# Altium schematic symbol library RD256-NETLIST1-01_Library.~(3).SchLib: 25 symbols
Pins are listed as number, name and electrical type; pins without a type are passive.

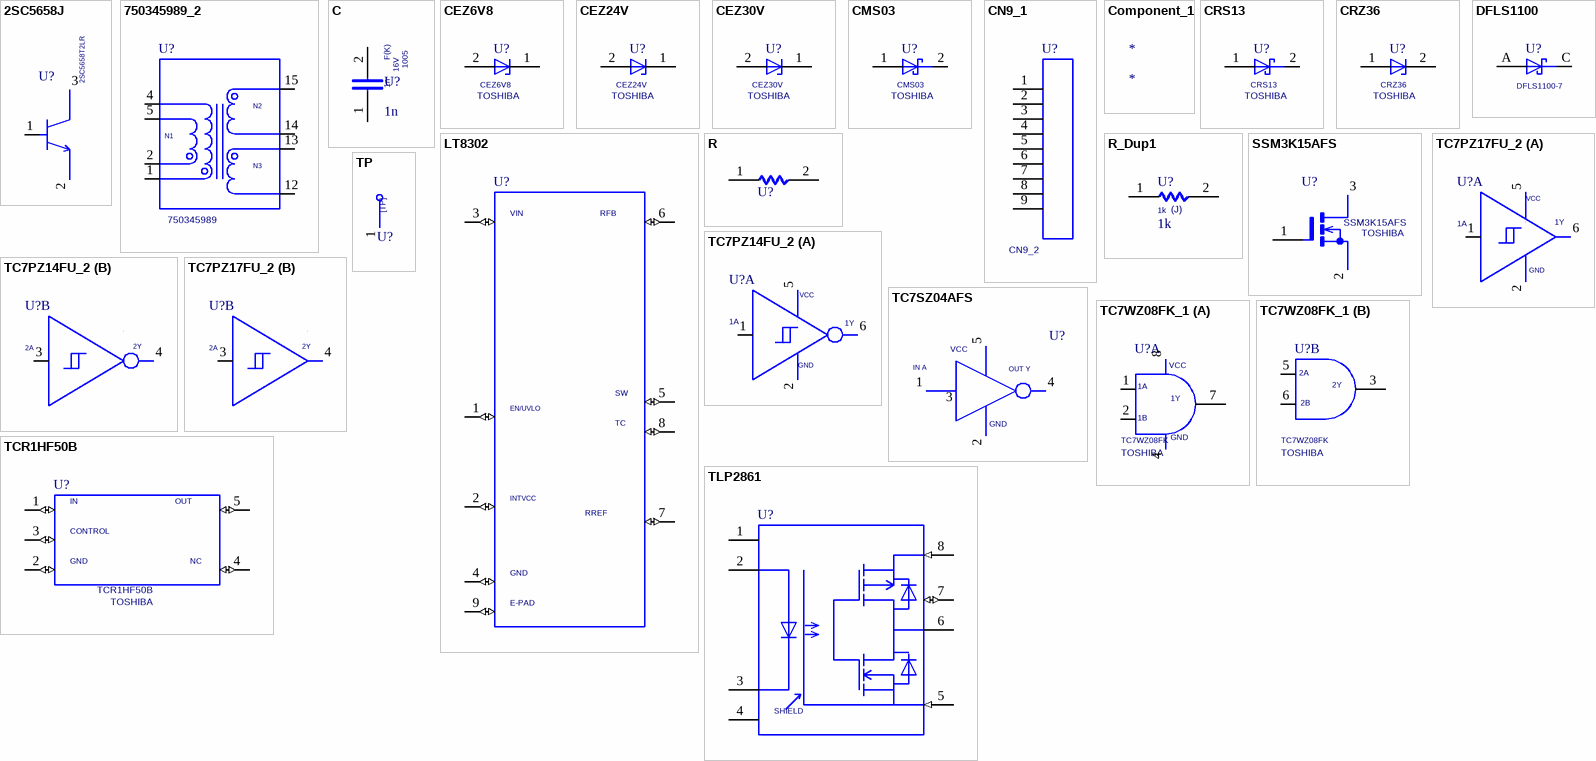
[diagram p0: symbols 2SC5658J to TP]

## 2SC5658J
designator U?, comment 2SC5658T2LR
TIME: 09:39:04; UPDATEUSER: 19910145; UPDATETIME: 15:12:10; SAVECOUNT: 8; COMP: 2SC5658J; VENDOR: ROHM; SAVEAREA0: -6194,-158,18648,15662; PSPICETEMPLATE: X^@REFDES %C %B %E @MODEL; ORIGINALSYMBOLORIGIN: (0,0); Altium-Right: 20; Altium-Bottom: 80
simulation model 2SC5658J
pins: 1 B, 2 E, 3 C

## 750345989_2
designator U?, comment 750345989
TIME: 11:55:02; UPDATEUSER: t5459927; UPDATETIME: 19:39:05; SAVECOUNT: 3; COMP: 750345989_2; PSPICETEMPLATE: X^@REFDES %1 %2 %3 %4 %5 %6 %7 %8 @MODEL; OriginalSymbolOrigin: (0,0); Altium-Right: 80; Altium-Bottom: 100
simulation model 750345989_2
pins: 1 4 (io), 2 5 (io), 4 1 (io), 5 2 (io), 12 (io), 13 (io), 14 (io), 15 (io)

## C
designator U?, comment 1n  VAL1: F(K)  SIZE: 1005  VOLTAGE: 16V
TIME: 11:55:01; UPDATEUSER: HP_Z8_KEYSHOT; SAVECOUNT: 2; COMP: C; TC1: 0; PSPICETEMPLATE: C^@REFDES %1 %2 ?TOLERANCE¦C^@REFDES¦ @VALUE ?IC/IC=@IC/ TC=@TC1,@TC2 ?TOLERANCE¦\n.model C^@REFDES CAP C=1 DEV=@TOLERANCE% TC1=@TC1 TC2=@TC2 VC1=@VC1 VC2=@VC2¦; ORIGINALSYMBOLORIGIN: (0,0); Altium-Right: 20; Altium-Bottom: 10
simulation model C
pins: 1, 2

## CEZ6V8
designator U?  VENDOR: TOSHIBA
TIME: 14:49:55; UPDATEUSER: fukuda-y; UPDATETIME: 08:18:42; SAVECOUNT: 6; SAVEAREA0: -4630,-153,17114,13055; PSPICETEMPLATE: X^@REFDES %A %C @MODEL; ORIGINALSYMBOLORIGIN: (0,0); Altium-Right: 10; Altium-Bottom: 20
simulation model CEZ6V8
pins: 1 C, 2 A

## CEZ24V
designator U?  VENDOR: TOSHIBA
TIME: 14:49:55; UPDATEUSER: fukuda-y; UPDATETIME: 08:18:42; SAVECOUNT: 6; SAVEAREA0: -4630,-153,17114,13055; PSPICETEMPLATE: X^@REFDES %A %C @MODEL; ORIGINALSYMBOLORIGIN: (0,0); Altium-Right: 10; Altium-Bottom: 20
simulation model CEZ24V
pins: 1 C, 2 A

## CEZ30V
designator U?  VENDOR: TOSHIBA
TIME: 14:49:55; UPDATEUSER: fukuda-y; UPDATETIME: 08:18:42; SAVECOUNT: 6; SAVEAREA0: -4630,-153,17114,13055; PSPICETEMPLATE: X^@REFDES %C %A @MODEL; ORIGINALSYMBOLORIGIN: (0,0); Altium-Right: 10; Altium-Bottom: 20
simulation model CEZ30V
pins: 1 C, 2 A

## CMS03
designator U?  VENDOR: TOSHIBA
TIME: 14:49:55; UPDATEUSER: fukuda-y; UPDATETIME: 08:16:22; SAVECOUNT: 9; SAVEAREA0: -4630,-153,17114,13055; PSPICETEMPLATE: X^@REFDES %A %C @MODEL; ORIGINALSYMBOLORIGIN: (0,0); Altium-Right: 20
simulation model CMS03
pins: 1 A, 2 C

## CN9_1
designator U?, comment CN9_2
TIME: 11:55:03; UPDATEUSER: HP_Z8_KEYSHOT; SAVECOUNT: 2; PSPICETEMPLATE: X^@REFDES %1 %2 %3 %4 %5 %6 %7 %8 %9 %10 %M1 %M2 @MODEL; COMP: CN9_1; USER_VALUE: XG4A-1031; OriginalSymbolOrigin: (0,0); Altium-Right: 20; Altium-Bottom: 120
simulation model CN9_1
pins: 1, 2, 3, 4, 5, 6, 7, 8, 9

## Component_1
designator *

## CRS13
designator U?  VENDOR: TOSHIBA
TIME: 14:49:55; UPDATEUSER: fukuda-y; UPDATETIME: 08:18:42; SAVECOUNT: 6; SAVEAREA0: -4630,-153,17114,13055; PSPICETEMPLATE: X^@REFDES %A %C @MODEL; ORIGINALSYMBOLORIGIN: (0,0); Altium-Right: 20
simulation model CRS13
pins: 1 A, 2 C

## CRZ36
designator U?  VENDOR: TOSHIBA
TIME: 14:49:55; UPDATEUSER: fukuda-y; UPDATETIME: 08:18:42; SAVECOUNT: 6; SAVEAREA0: -4630,-153,17114,13055; PSPICETEMPLATE: X^@REFDES %A %C @MODEL; ORIGINALSYMBOLORIGIN: (0,0); Altium-Right: 10; Altium-Bottom: 20
simulation model CRZ36
pins: 1 A, 2 C

## DFLS1100
designator U?, comment DFLS1100-7
TIME: 14:49:55; UPDATEUSER: fukuda-y; UPDATETIME: 08:18:42; SAVECOUNT: 6; SAVEAREA0: -4630,-153,17114,13055; PSPICETEMPLATE: X^@REFDES %C %A @MODEL; ORIGINALSYMBOLORIGIN: (0,0); Altium-Right: 20
simulation model DFLS1100
pins: A, C

## LT8302
designator U?, comment LT8302IS8E  (value not drawn)
TIME: 11:55:00; UPDATEUSER: t5459927; UPDATETIME: 18:09:57; SAVECOUNT: 8; COMP: LT8302; PSPICETEMPLATE: X^@REFDES %EN/UVLO %INTVCC %VIN %GND %SW %RFB %RREF %TC %EXPOSED_PAD @MODEL; OriginalSymbolOrigin: (0,0); Altium-Right: 100; Altium-Bottom: 290
simulation model LT8302
pins: 1 (io), 2 (io), 3 (io), 4 (io), 5 (io), 6 (io), 7 (io), 8 (io), 9 (io)

## R
designator U?  (value not drawn)
OriginalSymbolOrigin: (5080,5080); Altium-Right: 20
pins: 1, 2

## R_Dup1
designator U?, comment 1k  VAL1: (J)
TIME: 11:54:58; UPDATEUSER: HP_Z8_KEYSHOT; UPDATETIME: 11:54:59; SAVECOUNT: 2; WATT: 0.125; COMP: R; TC1: 0; PSPICETEMPLATE: R^@REFDES %1 %2 ?TOLERANCE¦R^@REFDES¦ @VALUE TC=@TC1,@TC2 ?TOLERANCE¦\n.model R^@REFDES RES R=1 DEV=@TOLERANCE% TC1=@TC1 TC2=@TC2¦; ORIGINALSYMBOLORIGIN: (0,0); Altium-Right: 20
simulation model R_Dup1
pins: 1, 2

## SSM3K15AFS
designator U?  VENDOR: TOSHIBA
TIME: 11:54:59; UPDATEUSER: HP_Z8_KEYSHOT; UPDATETIME: 11:55:00; SAVECOUNT: 2; ORIGINALSYMBOLORIGIN: (0,0); PSPICETEMPLATE: X^@REFDES %D %G %S @MODEL; Altium-Right: 30; Altium-Bottom: 70
simulation model SSM3K15AFS
pins: 1 G, 2 S, 3 D

## TC7PZ14FU_2
designator U?, comment TC7PZ17FU  (value not drawn)
TIME: 11:55:01; UPDATEUSER: t5459927; UPDATETIME: 19:09:34; SAVECOUNT: 7; SPLIT_INST: TRUE; PSPICETEMPLATE: X^@REFDES %1A %GND %2A %2Y %VCC %1Y @MODEL; COMP: TC7PZ17FU_2; VENDOR: TOSHIBA; SWAP_INFO: (S1+S2); OriginalSymbolOrigin: (5080,15240); Altium-Right: 70; Altium-Bottom: 60
simulation model TC7PZ14FU_2
part A pins: 1 (io), 2 (io), 5 (io), 6 (io)
part B pins: 3 (io), 4 (io)

## TC7PZ17FU_2
designator U?, comment TC7PZ17FU  (value not drawn)
TIME: 11:55:01; UPDATEUSER: t5459927; UPDATETIME: 15:05:08; SAVECOUNT: 4; SPLIT_INST: TRUE; PSPICETEMPLATE: X^@REFDES %1A %GND %2A %2Y %VCC %1Y @MODEL; COMP: TC7PZ17FU_2; VENDOR: TOSHIBA; SWAP_INFO: (S1+S2); OriginalSymbolOrigin: (5080,15240); Altium-Right: 60
simulation model TC7PZ17FU_2
part A pins: 1 (io), 2 (io), 5 (io), 6 (io)
part B pins: 3 (io), 4 (io)

## TC7SZ04AFS
designator U?  (value not drawn)
TIME: 11:55:02; UPDATEUSER: t5459927; UPDATETIME: 19:30:29; SAVECOUNT: 6; VENDOR: TOSHIBA; PSPICETEMPLATE: X^@REFDES %INA %GND %NC %OUTY %VCC @MODEL; OriginalSymbolOrigin: (0,-5080); Altium-Right: 80; Altium-Bottom: 60
simulation model TC7SZ04AFS
pins: 1 (io), 2 (io), 3 (io), 4 (io), 5 (io)

## TC7WZ08FK_1
designator U?, comment TC7WZ08FK  VENDOR: TOSHIBA
TIME: 08:52:39; UPDATEUSER: sptcae09; UPDATETIME: 16:09:46; SAVECOUNT: 9; SWAP_INFO: (S1+S2); COMP: TC7WZ08FK_2; ORDER: $pOrder; SPLIT_INST: TRUE; ・: 20mA; USER_VALUE: TC7W00FK; PSPICETEMPLATE: X^@REFDES %1A %1B %2Y %GND %2A %2B %1Y %VCC @MODEL; DESCRIPTION-A: NAND 2ch Logic; ORIGINALSYMBOLORIGIN: (2540,-2540); Altium-Right: 40; Altium-Bottom: 60
simulation model TC7WZ08FK_1
part A pins: 1, 2, 4, 7, 8
part B pins: 3, 5, 6

## TCR1HF50B
designator U?  VENDOR: TOSHIBA
TIME: 11:54:59; UPDATEUSER: t5459927; UPDATETIME: 10:27:35; SAVECOUNT: 4; PSPICETEMPLATE: X^@REFDES %IN %GND %CONTROL %NC %OUT @MODEL; OriginalSymbolOrigin: (-2540,0); Altium-Right: 110; Altium-Bottom: 60
simulation model TCR1HF50B
pins: 1 (io), 2 (io), 3 (io), 4 (io), 5 (io)

## TLP2861
designator U?, comment TLP2861L  (value not drawn)
TIME: 11:54:59; UPDATEUSER: t5459927; UPDATETIME: 10:22:13; SAVECOUNT: 4; VENDOR: TOSHIBA; PSPICETEMPLATE: X^@REFDES %1 %2 %3 %4 %5 %6 %7 %8 @MODEL; SAVEAREA0: -29717,-10800,67926,51382; OriginalSymbolOrigin: (5080,35560); Altium-Right: 110; Altium-Bottom: 140
simulation model TLP2861
pins: 1, 2, 3, 4, 5 (in), 6, 7 (io), 8 (in)

## TP
designator U?  (value not drawn)
TIME: 16:12:21; UPDATEUSER: fukuda-y; UPDATETIME: 16:18:11; SAVECOUNT: 2; SAVEAREA0: -242,-92,12810,7836; ORIGINALSYMBOLORIGIN: (0,0); Altium-Right: 20; Altium-Bottom: 30
pins: 1

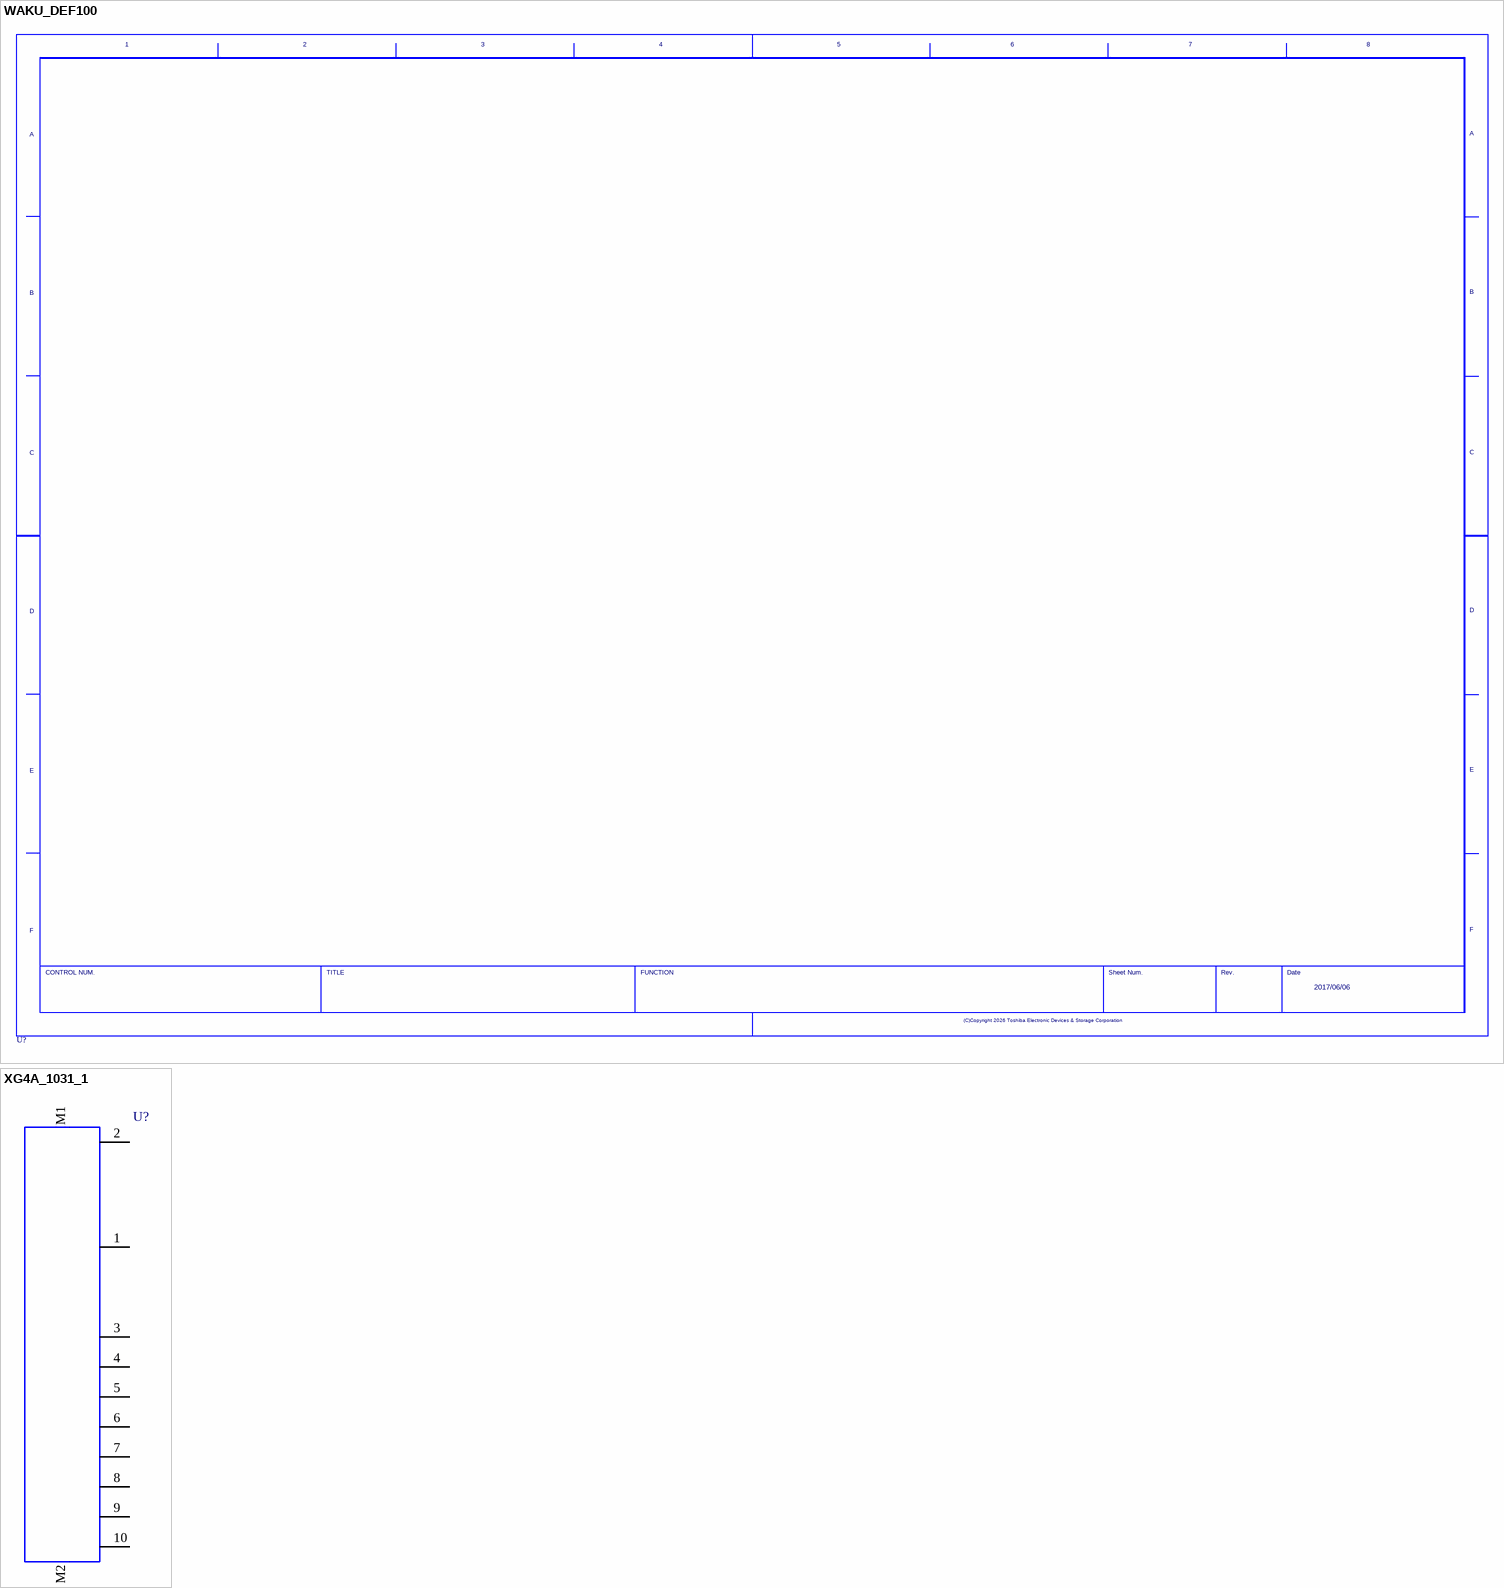
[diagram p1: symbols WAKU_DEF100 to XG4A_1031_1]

## WAKU_DEF100
designator U?  DATE: 2017/06/06  (hidden comment: WAKU_DEF100)
PLOTTIME: HH:MM; SAVEAREA0: -63393,-16950,474261,314592; TIME: 14:30:25; UPDATEUSER: t5459927; UPDATETIME: 19:33:03; SAVECOUNT: 5; OriginalSymbolOrigin: (10160,284480); Altium-Right: 1570; Altium-Bottom: 1070

## XG4A_1031_1
designator U?, comment XG4A_1031  (value not drawn)
PART NUMBER: XG4A-1031; TIME: 11:54:59; UPDATEUSER: t5459927; UPDATETIME: 17:44:51; SAVECOUNT: 12; PSPICETEMPLATE: X^@REFDES %1 %2 %3 %4 %5 %6 %7 %8 %9 %10 %M1 %M2 @MODEL; OriginalSymbolOrigin: (0,73660); Altium-Right: 50; Altium-Bottom: 290
simulation model XG4A_1031_1
pins: 1, 2, 3, 4, 5, 6, 7, 8, 9, 10, M1, M2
